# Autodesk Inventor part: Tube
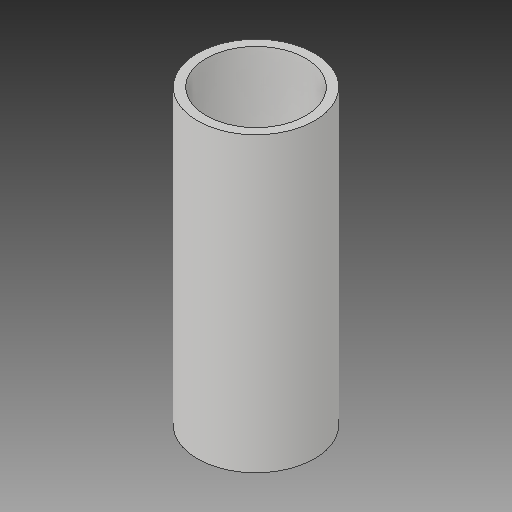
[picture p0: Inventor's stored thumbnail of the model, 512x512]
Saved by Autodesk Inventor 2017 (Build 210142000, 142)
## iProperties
Created: 2020-03
Part Number: Tube
Material: Generic
Document SubType Name: Modeling
Designer: user
Density: 1 g/cm^3
Appearance: Default
Mass: 4.35896 g
Surface Area: 59.863 cm^2
Volume: 4.35896 cm^3
Author: user
Revision Number: ANY
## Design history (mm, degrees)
feature "Revolve1"
body "Solid1"
